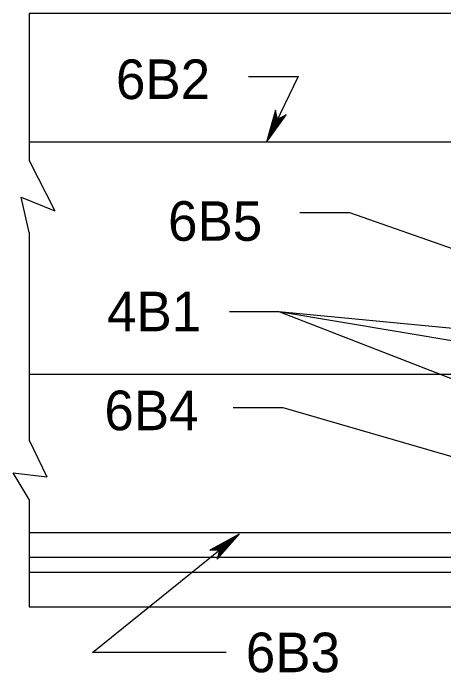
# Model space of a CAD drawing. Extents: x 499883 to 500983, y 499104 to 499764.
# Drawn here: x 500012.6 to 500056.1, y 499574.5 to 499641.2 of the extents above; entities that cross this region are included whole.
import ezdxf

# ---------------------------------------------------------------- set-up
doc = ezdxf.new("R2010")
doc.units = 0
doc.layers.add('5', color=7, linetype='Continuous')

msp = doc.modelspace()

# ---------------------------------------------------------------- linework, layer by layer
at = {"layer": '5'}
for p, q in [((500014.216, 499641.156), (500087.439, 499641.156)), ((500014.216, 499641.156), (500014.216, 499626.284)), ((500036.391, 499634.768), (500041.388, 499634.768)), ((500041.388, 499634.768), (500038.218, 499628.135)), ((500014.216, 499628.167), (500085.44, 499628.167)), ((500014.216, 499626.284), (500016.803, 499621.193)), ((500014.216, 499618.997), (500013.409, 499622.591)), ((500013.409, 499622.591), (500016.803, 499621.193)), ((500041.582, 499621.022), (500046.578, 499621.022)), ((500046.578, 499621.022), (500060.517, 499616.121)), ((500014.216, 499618.997), (500014.216, 499598.034)), ((500034.469, 499611.026), (500039.465, 499611.026)), ((500039.465, 499611.026), (500083.279, 499606.856)), ((500039.465, 499611.026), (500071.389, 499605.679)), ((500039.465, 499611.026), (500060.794, 499602.736)), ((500014.216, 499604.685), (500095.433, 499604.685)), ((500034.853, 499601.319), (500039.85, 499601.319)), ((500039.85, 499601.319), (500060.709, 499595.264)), ((500014.216, 499598.034), (500016.005, 499594.341)), ((500014.216, 499592.045), (500012.611, 499594.74)), ((500012.611, 499594.74), (500016.005, 499594.341)), ((500014.216, 499592.045), (500014.216, 499581.202)), ((500014.216, 499588.697), (500085.44, 499588.697)), ((500020.614, 499576.59), (500035.43, 499588.535)), ((500014.216, 499586.199), (500095.433, 499586.199)), ((500014.216, 499584.699), (500095.433, 499584.699)), ((500014.216, 499581.202), (500095.433, 499581.202)), ((500034.145, 499576.59), (500020.614, 499576.59))]:
    msp.add_line(p, q, dxfattribs=at)
for points in [[(500038.218, 499628.135), (500040.181, 499630.881), (500039.308, 499630.418), (500039.122, 499631.368), (500038.218, 499628.135), (500038.308, 499628.337), (500040.102, 499630.815), (500039.275, 499630.365), (500039.105, 499631.227), (500038.349, 499628.449), (500038.412, 499628.542), (500039.937, 499630.671), (500039.268, 499630.349), (500039.118, 499631.081), (500038.434, 499628.587), (500038.466, 499628.694), (500039.806, 499630.553), (500039.265, 499630.325), (500039.092, 499630.904), (500038.605, 499628.984), (500038.686, 499629.153), (500039.658, 499630.438), (500039.257, 499630.289), (500039.102, 499630.73), (500038.715, 499629.176), (500038.801, 499629.332), (500039.496, 499630.315), (500039.19, 499630.209), (500039.091, 499630.53), (500038.862, 499629.484), (500038.95, 499629.627), (500039.38, 499630.211), (500039.184, 499630.175), (500039.108, 499630.427), (500038.972, 499629.713), (500039.272, 499630.084), (500039.128, 499630.079), (500039.101, 499630.318), (500039.007, 499629.826), (500039.207, 499630.068), (500039.062, 499629.996), (500039.071, 499630.154), (500039.092, 499629.982), (500039.141, 499630.044)], [(500035.43, 499588.535), (500032.474, 499586.906), (500033.461, 499586.947), (500033.219, 499586.01), (500035.43, 499588.535), (500035.262, 499588.392), (500032.574, 499586.931), (500033.514, 499586.981), (500033.295, 499586.129), (500035.176, 499588.309), (500035.079, 499588.252), (500032.785, 499586.991), (500033.527, 499586.992), (500033.347, 499586.267), (500035.04, 499588.221), (500034.964, 499588.139), (500032.954, 499587.041), (500033.54, 499587.012), (500033.447, 499586.416), (500034.715, 499587.937), (500034.569, 499587.819), (500033.137, 499587.081), (500033.563, 499587.042), (500033.513, 499586.577), (500034.532, 499587.811), (500034.388, 499587.708), (500033.336, 499587.121), (500033.659, 499587.085), (500033.609, 499586.753), (500034.267, 499587.597), (500034.126, 499587.505), (500033.486, 499587.164), (500033.678, 499587.113), (500033.638, 499586.853), (500034.069, 499587.438), (500033.638, 499587.232), (500033.77, 499587.175), (500033.691, 499586.948), (500033.989, 499587.351), (500033.704, 499587.219), (500033.866, 499587.221), (500033.789, 499587.083), (500033.844, 499587.248), (500033.774, 499587.212)]]:
    msp.add_lwpolyline(points, dxfattribs=at)

# ---------------------------------------------------------------- texts
for s, p in [('6B2', (500022.994, 499632.482)), ('6B5', (500028.258, 499618.167)), ('4B1', (500022.091, 499609.026)), ('6B4', (500021.825, 499599.034)), ('6B3', (500036.114, 499574.59))]:
    msp.add_text(s, height=4, dxfattribs=at).set_placement(p)

doc.saveas('drawing.dxf')
